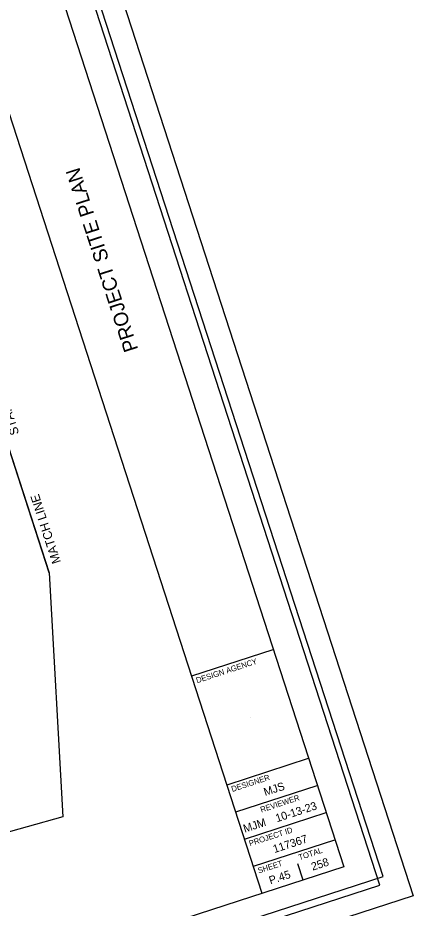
# Model space of a CAD drawing. Extents: x -468556195 to 3353078, y -306091294 to 1252632.
# Drawn here: x 1834891 to 1836968, y 532729 to 537403 of the extents above; entities that cross this region are included whole.
import ezdxf

# ---------------------------------------------------------------- set-up
doc = ezdxf.new("R2010")
doc.units = 0
for name, color, linetype in [('DT_X_Terrain_Ground_Line', 7, 'Continuous'), ('Level 63', 7, 'Continuous'), ('SC_Scratch1', 7, 'Continuous'), ('SH_Border', 7, 'Continuous'), ('SH_Cut_Line', 7, 'Continuous'), ('SH_Data', 7, 'Continuous')]:
    doc.layers.add(name, color=color, linetype=linetype)

msp = doc.modelspace()

# ---------------------------------------------------------------- linework, layer by layer
at = {"layer": 'DT_X_Terrain_Ground_Line'}
msp.add_line((1835055.9, 534489.2), (1834448.3, 536360.7), dxfattribs=at)
at = {"layer": 'Level 63'}
for points in [[(1825229.4, 535921.9), (1834930.2, 539071.3), (1836968, 532794.6), (1827267.2, 529645.1)], [(1827336.2, 529818.9), (1836809.4, 532894.5), (1834849.2, 538932.3), (1825375.9, 535856.7)]]:
    msp.add_lwpolyline(points, close=True, dxfattribs=at)
at = {"layer": 'SC_Scratch1'}
msp.add_lwpolyline([(1826839.3, 533890.1), (1826769.8, 534863.1), (1833950.4, 537284.3), (1834448.3, 536360.7), (1835055.9, 534489.2), (1835128.1, 533209.3), (1827818.5, 531160.4), (1827446.8, 532019.1)], close=True, dxfattribs=at)
at = {"layer": 'SH_Border'}
for p, q in [((1836175.1, 532806.4), (1834229.7, 538798.6)), ((1835804.6, 533947.8), (1836232.6, 534086.8)), ((1835989.9, 533377.1), (1836417.9, 533516.1)), ((1836036.2, 533234.4), (1836464.2, 533373.4)), ((1836082.5, 533091.8), (1836510.5, 533230.7)), ((1836128.8, 532949.1), (1836556.8, 533088.1))]:
    msp.add_line(p, q, dxfattribs=at)
msp.add_lwpolyline([(1825526.9, 535973.1), (1834657.8, 538937.5), (1836603.1, 532945.4), (1827472.3, 529981)], close=True, dxfattribs=at)
at = {"layer": 'SH_Cut_Line'}
msp.add_lwpolyline([(1827090.6, 529699.4), (1836792.1, 532849), (1834754.1, 539126.5), (1825052.6, 535976.8)], close=True, dxfattribs=at)
at = {"layer": 'SH_Data'}
for p, q in [((1836111.2, 533731.9), (1836111.2, 533731.9)), ((1836389.1, 532875.9), (1836361.3, 532961.5)), ((1836265.9, 532891.1), (1836265.9, 532891.1))]:
    msp.add_line(p, q, dxfattribs=at)

# ---------------------------------------------------------------- texts
at = {"layer": 'DT_X_Terrain_Ground_Line'}
msp.add_text('MATCH LINE                   STA. 1690+00', height=46.8, rotation=107.9864, dxfattribs=at).set_placement((1835117.7, 534546))
at = {"layer": 'SH_Data'}
for s, height, rotation, p in [('PROJECT SITE PLAN', 75, 107.9864, (1835523.8, 535662.9)), ('DESIGN AGENCY', 30, 17.9864, (1835832.7, 533909.6)), ('DESIGNER', 30, 17.9864, (1836018, 533338.9)), ('MJS', 42, 17.9864, (1836190.2, 533317.6)), ('REVIEWER', 30, 17.9864, (1836170.4, 533230.7)), ('10-13-23', 42, 17.9864, (1836252.2, 533180)), ('MJM', 42, 17.9864, (1836082.9, 533125)), ('PROJECT ID', 30, 17.9864, (1836110.7, 533053.6)), ('117367', 42, 17.9864, (1836238.9, 533018)), ('TOTAL', 30, 17.9864, (1836371, 532980.4)), ('SHEET', 30, 17.9864, (1836157, 532910.9)), ('258', 42, 17.9864, (1836439.9, 532925.5)), ('P.45', 42, 17.9864, (1836218.1, 532853.5))]:
    msp.add_text(s, height=height, rotation=rotation, dxfattribs=at).set_placement(p)

doc.saveas('drawing.dxf')
